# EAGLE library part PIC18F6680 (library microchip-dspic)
PIC18F Flash Microcontroller with CAN port
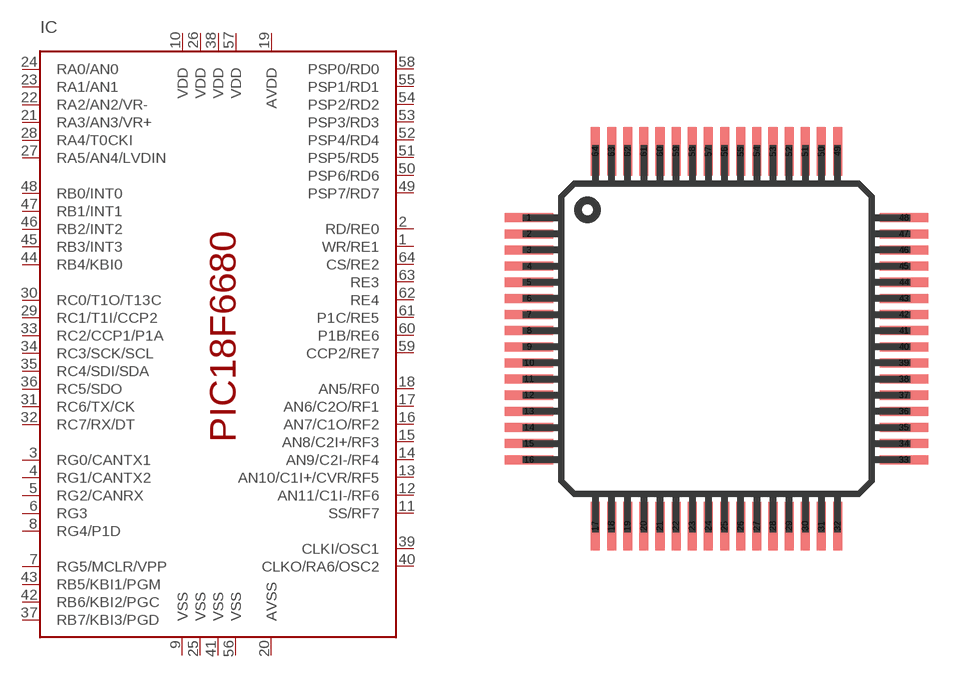
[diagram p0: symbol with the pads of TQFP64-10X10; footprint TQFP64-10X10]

Designator prefix IC

## PIC18F6680TQ-64  [TQFP64-10X10]
1  WR/RE1
2  RD/RE0
3  RG0/CANTX1
4  RG1/CANTX2
5  RG2/CANRX
6  RG3
7  RG5/MCLR/VPP
8  RG4/P1D
9  VSS  pwr
10  VDD  pwr
11  SS/RF7
12  AN11/C1I-/RF6
13  AN10/C1I+/CVR/RF5
14  AN9/C2I-/RF4
15  AN8/C2I+/RF3
16  AN7/C1O/RF2
17  AN6/C2O/RF1
18  AN5/RF0
19  AVDD  pwr
20  AVSS  pwr
21  RA3/AN3/VR+
22  RA2/AN2/VR-
23  RA1/AN1
24  RA0/AN0
25  VSS  pwr
26  VDD  pwr
27  RA5/AN4/LVDIN
28  RA4/T0CKI
29  RC1/T1I/CCP2
30  RC0/T1O/T13C
31  RC6/TX/CK
32  RC7/RX/DT
33  RC2/CCP1/P1A
34  RC3/SCK/SCL
35  RC4/SDI/SDA
36  RC5/SDO
37  RB7/KBI3/PGD
38  VDD  pwr
39  CLKI/OSC1  in
40  CLKO/RA6/OSC2  out
41  VSS  pwr
42  RB6/KBI2/PGC
43  RB5/KBI1/PGM
44  RB4/KBI0
45  RB3/INT3
46  RB2/INT2
47  RB1/INT1
48  RB0/INT0
49  PSP7/RD7
50  PSP6/RD6
51  PSP5/RD5
52  PSP4/RD4
53  PSP3/RD3
54  PSP2/RD2
55  PSP1/RD1
56  VSS  pwr
57  VDD  pwr
58  PSP0/RD0
59  CCP2/RE7
60  P1B/RE6
61  P1C/RE5
62  RE4
63  RE3
64  CS/RE2

## Footprint TQFP64-10X10 (pad centres in mm)
Thin Quad Flat Pack package type TQ
smd 1.5 x 0.28: 1 -5.8,3.75; 2 -5.8,3.25; 3 -5.8,2.75; 4 -5.8,2.25; 5 -5.8,1.75; 6 -5.8,1.25; 7 -5.8,0.75; 8 -5.8,0.25; 9 -5.8,-0.25; 10 -5.8,-0.75; 11 -5.8,-1.25; 12 -5.8,-1.75; 13 -5.8,-2.25; 14 -5.8,-2.75; 15 -5.8,-3.25; 16 -5.8,-3.75; 33 5.8,-3.75; 34 5.8,-3.25; 35 5.8,-2.75; 36 5.8,-2.25; 37 5.8,-1.75; 38 5.8,-1.25; 39 5.8,-0.75; 40 5.8,-0.25; 41 5.8,0.25; 42 5.8,0.75; 43 5.8,1.25; 44 5.8,1.75; 45 5.8,2.25; 46 5.8,2.75; 47 5.8,3.25; 48 5.8,3.75
smd 0.28 x 1.5: 17 -3.75,-5.8; 18 -3.25,-5.8; 19 -2.75,-5.8; 20 -2.25,-5.8; 21 -1.75,-5.8; 22 -1.25,-5.8; 23 -0.75,-5.8; 24 -0.25,-5.8; 25 0.25,-5.8; 26 0.75,-5.8; 27 1.25,-5.8; 28 1.75,-5.8; 29 2.25,-5.8; 30 2.75,-5.8; 31 3.25,-5.8; 32 3.75,-5.8; 49 3.75,5.8; 50 3.25,5.8; 51 2.75,5.8; 52 2.25,5.8; 53 1.75,5.8; 54 1.25,5.8; 55 0.75,5.8; 56 0.25,5.8; 57 -0.25,5.8; 58 -0.75,5.8; 59 -1.25,5.8; 60 -1.75,5.8; 61 -2.25,5.8; 62 -2.75,5.8; 63 -3.25,5.8; 64 -3.75,5.8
